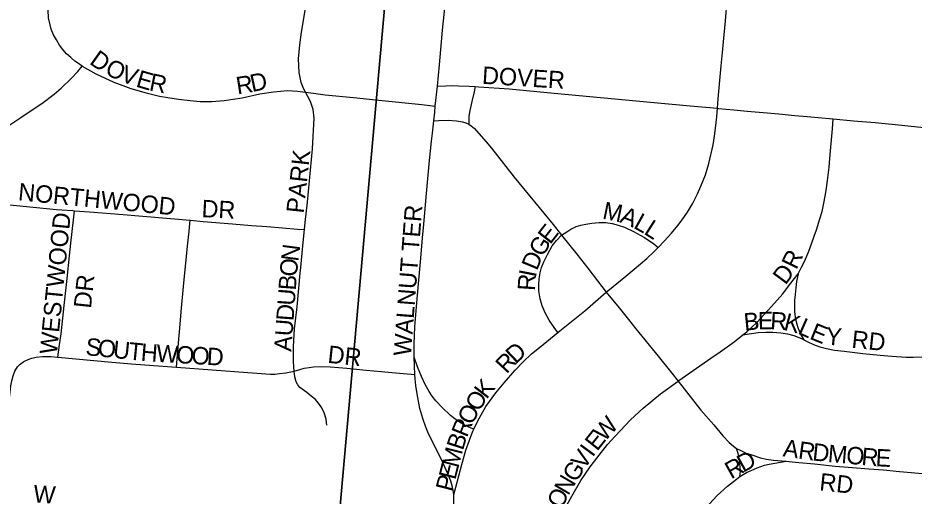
# Model space of a CAD drawing. Extents: x 1410790 to 1770854, y 566777 to 831614.
# Drawn here: x 1598681 to 1601254, y 711577 to 712950 of the extents above; entities that cross this region are included whole.
import ezdxf

# ---------------------------------------------------------------- set-up
doc = ezdxf.new("R2010")
doc.units = 0
for name, color, linetype in [('GM_X_City_Street', 7, 'Continuous'), ('GM_X_City_Street_Text', 7, 'Continuous'), ('GM_X_Section', 7, 'Continuous')]:
    doc.layers.add(name, color=color, linetype=linetype)

msp = doc.modelspace()

# ---------------------------------------------------------------- linework, layer by layer
at = {"layer": 'GM_X_City_Street'}
for points in [[(1598865.3, 712811.4), (1598854.5, 712818.6), (1598844.1, 712826), (1598832.2, 712836.3), (1598820.1, 712846.7), (1598809.7, 712858.9), (1598800.1, 712871.5), (1598790.9, 712887.2), (1598782.9, 712901.4), (1598776.4, 712917.5), (1598772.8, 712930.1), (1598768.8, 712949.7), (1598767, 712972.3), (1598767, 712997.4), (1598768.8, 713027.8), (1598772.3, 713065.1), (1598781.8, 713135.5), (1598793.9, 713218.8), (1598806.2, 713312.7), (1598811, 713349.6)], [(1599506.7, 712736.3), (1599502, 712745.5), (1599494.2, 712764.6), (1599487.7, 712793.3), (1599486.3, 712832.4), (1599489.6, 712873), (1599494.7, 712908.9), (1599499.2, 712936.5), (1599506.5, 712977.6), (1599517.3, 713026.1), (1599526.9, 713066), (1599533.4, 713090.3), (1599539.1, 713106), (1599545.4, 713118.8), (1599554.5, 713131.3)], [(1599885.1, 712754), (1599890.8, 712815.1), (1599894.9, 712859.4), (1599900.1, 712914.8), (1599904.3, 712960.1), (1599908.1, 713000.8), (1599912.1, 713043.4), (1599916.9, 713096.3)], [(1600689.3, 712690.3), (1600691.6, 712717.1), (1600695.4, 712759.4), (1600700.2, 712812.5), (1600703.9, 712850.6), (1600706.8, 712881.1), (1600712.6, 712941), (1600717.3, 713001.2), (1600718.7, 713016.4), (1600719.2, 713023)], [(1598545.1, 712428.3), (1598547.2, 712432.3), (1598553.1, 712446.6), (1598557.4, 712461), (1598559.9, 712475.1), (1598561.2, 712488.5), (1598563.6, 712510.4), (1598566.7, 712528.9), (1598570.8, 712542.6), (1598577.1, 712557.3), (1598585.1, 712571.2), (1598595.3, 712586.2), (1598605.9, 712599.9), (1598618.2, 712612.6), (1598637.2, 712629.4), (1598660.1, 712645.2), (1598689.1, 712663.7), (1598713.3, 712680.1), (1598749.6, 712704.4), (1598784.5, 712730.8), (1598805, 712748), (1598832.6, 712774.5), (1598852.7, 712796.1), (1598865.3, 712811.4)], [(1598865.3, 712811.4), (1598903.9, 712789.4), (1598956.3, 712765.6), (1599004.9, 712747.4), (1599049.2, 712734.4), (1599087.1, 712725.5), (1599111.4, 712721.2), (1599141.8, 712716.8), (1599174.8, 712712.5), (1599204.3, 712709.9), (1599237.3, 712709.9), (1599272.9, 712712.5), (1599324.1, 712720.3), (1599375.3, 712731.6), (1599414.4, 712737.7), (1599454.3, 712741.2), (1599482.9, 712739.4), (1599506.7, 712736.3)], [(1599879.1, 712696.8), (1599885.1, 712754)], [(1599885.1, 712754), (1599909, 712755.2), (1599929.6, 712755.4), (1599945.6, 712755.1), (1599976.5, 712753.6), (1599994, 712752.8)], [(1599994, 712752.8), (1599990.4, 712738), (1599983.6, 712710.2), (1599977.9, 712683.7), (1599975.7, 712667.7), (1599975.4, 712657.7), (1599975.8, 712644.8)], [(1599994, 712752.8), (1600003.6, 712752.3), (1600090.8, 712746.6), (1600220.8, 712734), (1600497.3, 712708.2), (1600611.3, 712697.7), (1600689.3, 712690.3)], [(1599503.6, 712342.1), (1599505.6, 712362.2), (1599511.6, 712420.9), (1599526.3, 712574.5), (1599531.6, 712662.3), (1599528.1, 712687.4), (1599520.3, 712709.9), (1599512.7, 712724.5), (1599506.7, 712736.3)], [(1599506.7, 712736.3), (1599528.9, 712733.4), (1599562.9, 712729.3), (1599644.6, 712721.7), (1599726.4, 712713.1), (1599840.7, 712700.9), (1599879.1, 712696.8)], [(1599874.5, 712654.7), (1599877.3, 712679.5), (1599879.1, 712696.8)], [(1600519.3, 712291), (1600537.4, 712309.9), (1600557.3, 712331.6), (1600575.5, 712354.1), (1600587.7, 712369.8), (1600603.3, 712392.3), (1600618.1, 712415.8), (1600632, 712444.4), (1600641.5, 712467), (1600654.5, 712499.1), (1600664.9, 712532.1), (1600676.8, 712585.2), (1600682.2, 712617.4), (1600687.1, 712666.2), (1600689.3, 712690.3)], [(1600689.3, 712690.3), (1600692.6, 712690), (1600736.6, 712686), (1600774.8, 712682.5), (1600820.7, 712678.3), (1600865.1, 712674.3), (1600911.9, 712670), (1600946.6, 712666.8), (1600978.9, 712663.9), (1601021.6, 712660)], [(1599818.2, 711976), (1599818.6, 712014.3), (1599820.5, 712063), (1599827, 712143.8), (1599832.8, 712207.3), (1599837.5, 712260.3), (1599842.7, 712318.5), (1599846.2, 712357.5), (1599853.2, 712435.2), (1599862.8, 712540.6), (1599868.5, 712595.6), (1599870.8, 712618.7), (1599874.5, 712654.7)], [(1599874.5, 712654.7), (1599889.1, 712655.2), (1599916, 712656.1), (1599940.3, 712654.3), (1599956.9, 712652), (1599966.8, 712648.7), (1599975.8, 712644.8)], [(1599975.8, 712644.8), (1599981.9, 712640.2), (1599991.5, 712632.3), (1600004.3, 712618.4), (1600025, 712594.1), (1600040.4, 712575.6), (1600075.1, 712531.7), (1600105.1, 712492.4), (1600217.8, 712356.7), (1600241.5, 712326)], [(1600920.9, 712215.5), (1600931.1, 712234.2), (1600939.9, 712252.5), (1600951.7, 712280.4), (1600959.4, 712301.1), (1600967.2, 712323.7), (1600973.3, 712341.1), (1600983.7, 712373.2), (1600989.8, 712394), (1600995, 712417.7), (1600998.8, 712437.7), (1601001.1, 712454.9), (1601005.5, 712482.7), (1601009.8, 712521.5), (1601012.1, 712546.2), (1601014.2, 712568.6), (1601019.2, 712631), (1601021.6, 712660)], [(1601021.6, 712660), (1601080.3, 712654.8), (1601141.7, 712649.3), (1601209.6, 712642.7), (1601291.2, 712634.6), (1601357.1, 712628), (1601395.4, 712624.2), (1601425, 712621.2), (1601461.5, 712617.6), (1601488.4, 712614.3)], [(1598545.1, 712428.3), (1598565.9, 712423.3), (1598585.7, 712420.3), (1598629.4, 712415.1), (1598666.7, 712412.2), (1598790.9, 712400.1), (1598806.4, 712398.8), (1598838.1, 712396.8), (1598842.7, 712396.4)], [(1598795.3, 711975.8), (1598800.2, 712011.2), (1598804.6, 712043.4), (1598813.3, 712124), (1598821.7, 712201.8), (1598828.7, 712266.8), (1598832.6, 712303.1), (1598839.8, 712370.1), (1598842.7, 712396.4)], [(1598842.7, 712396.4), (1598886, 712393.4), (1598982.9, 712385.6), (1599175.1, 712368.8)], [(1599136, 711947.5), (1599139.9, 711994.2), (1599142.7, 712027.7), (1599145.3, 712059.1), (1599149.2, 712105.8), (1599156.4, 712178.4), (1599162.2, 712237.3), (1599168.7, 712303.2), (1599172, 712337.3), (1599175.1, 712368.8)], [(1599175.1, 712368.8), (1599212.2, 712365.5), (1599296.3, 712358.8), (1599351, 712354.4), (1599395.2, 712350.8), (1599440.4, 712347.2), (1599483, 712343.8), (1599503.6, 712342.1)], [(1600241.5, 712326), (1600256.3, 712336.1), (1600268.6, 712343.9), (1600283.2, 712350.9), (1600297.1, 712355.2), (1600311.2, 712357.5), (1600328.3, 712360.4), (1600349.2, 712362.1), (1600368.3, 712362.1), (1600386.5, 712359.5), (1600403.7, 712355), (1600422.2, 712348.9), (1600448, 712337.1), (1600479.5, 712319.9), (1600506.3, 712301.4), (1600519.3, 712291)], [(1599474, 711935.6), (1599472.8, 711948.5), (1599471.6, 711963.4), (1599471.7, 711986.2), (1599471.7, 712007), (1599475.2, 712057.3), (1599482.3, 712120.2), (1599491.2, 712217), (1599492.5, 712233.1), (1599498.8, 712295.2), (1599503.6, 712342.1)], [(1600231.1, 712046.4), (1600220.6, 712060.9), (1600206.4, 712081.9), (1600194.7, 712102.9), (1600186, 712123.2), (1600180.5, 712143.6), (1600176.6, 712166.7), (1600176.2, 712183.6), (1600177.5, 712200.7), (1600180.5, 712218.2), (1600184.2, 712233.6), (1600191, 712249.6), (1600200.8, 712270.6), (1600214.7, 712295.4), (1600226.7, 712311.2), (1600241.5, 712326)], [(1600241.5, 712326), (1600285.2, 712271.9), (1600316.9, 712231), (1600344.7, 712195.1), (1600369.9, 712162.6)], [(1600369.9, 712162.6), (1600389.7, 712178.9), (1600425.9, 712208.7), (1600450.5, 712228.3), (1600486.1, 712259.5), (1600507, 712278.6), (1600519.3, 712291)], [(1600761.7, 712039.8), (1600773.6, 712049.1), (1600802.3, 712075.5), (1600844.1, 712121.1), (1600876.6, 712157.8), (1600896.4, 712183.7), (1600920.9, 712215.5)], [(1600920.9, 712215.5), (1600916.6, 712193.3), (1600914.2, 712175.5), (1600912.4, 712156), (1600910.7, 712139), (1600910.7, 712122.8), (1600910.7, 712106.7), (1600912.4, 712090.5), (1600915.9, 712073.5), (1600920.9, 712058.2), (1600928.6, 712040.3), (1600937, 712026.2)], [(1600231.1, 712046.4), (1600236.9, 712051.2), (1600308.5, 712109.2), (1600369.9, 712162.6)], [(1600369.9, 712162.6), (1600406.8, 712117.2), (1600433.5, 712084.5), (1600455.3, 712057.7), (1600518.7, 711979.1), (1600558.4, 711929.8), (1600576.5, 711907.4)], [(1599989.5, 711769), (1600001.8, 711795.1), (1600010.4, 711810.7), (1600024.3, 711834.2), (1600053, 711873.2), (1600076.6, 711902), (1600108.7, 711939.1), (1600131.6, 711962.6), (1600155.3, 711985.2), (1600178.4, 712003.8), (1600231.1, 712046.4)], [(1600576.5, 711907.4), (1600578.2, 711908.7), (1600670.7, 711973.1), (1600697.5, 711991.4), (1600737, 712020.2), (1600761.7, 712039.8)], [(1600761.7, 712039.8), (1600780.8, 712042.8), (1600806.3, 712046.7), (1600827.8, 712047.6), (1600848.6, 712047.6), (1600871.7, 712046), (1600890.9, 712042.8), (1600908.4, 712038), (1600930.8, 712029.2), (1600937, 712026.2)], [(1600937, 712026.2), (1600949.2, 712020.4), (1600965.1, 712012.4), (1600983.5, 712005.2), (1601002.6, 712000.4), (1601025.8, 711996.4), (1601052.9, 711993.3), (1601107.2, 711986.9), (1601156.7, 711982.1), (1601190.2, 711978.9), (1601230.9, 711975.7), (1601251.7, 711975.7), (1601285.2, 711976.5), (1601314.3, 711977.2)], [(1598652.3, 711823.5), (1598658.1, 711876.3), (1598660.2, 711893.4), (1598662.6, 711908.1), (1598666.5, 711922.8), (1598671.6, 711935.4), (1598679.4, 711948.2), (1598686.9, 711956.3), (1598697.7, 711963.8), (1598709.7, 711969.2), (1598720.8, 711973.4), (1598732.5, 711976.1), (1598750.8, 711978.1), (1598775.4, 711977.5), (1598795.3, 711975.8)], [(1598795.3, 711975.8), (1598950.6, 711961.6), (1599006.6, 711957.1), (1599045.3, 711954.1), (1599136, 711947.5)], [(1599820.4, 711926.2), (1599818.2, 711976)], [(1599989.5, 711769), (1599982, 711772.4), (1599964.6, 711780.2), (1599948.1, 711789.8), (1599934.9, 711798.9), (1599922.4, 711808.9), (1599899.1, 711831.2), (1599880.7, 711850.2), (1599870, 711864.1), (1599861.4, 711877.1), (1599850.2, 711897.3), (1599839.6, 711920.8), (1599828.4, 711948.6), (1599818.2, 711976)], [(1599474, 711935.6), (1599490.3, 711940.5), (1599502.9, 711944), (1599516.5, 711946.8), (1599528.9, 711948.6), (1599552.3, 711949.3), (1599577.6, 711948.4), (1599625.3, 711944), (1599680.7, 711939), (1599724.1, 711935), (1599754.6, 711932.2), (1599788.2, 711929.1), (1599820.4, 711926.2)], [(1599136, 711947.5), (1599340.8, 711931.8), (1599405.6, 711927.5), (1599418.6, 711927.6), (1599431.7, 711928.7), (1599450, 711930.7), (1599474, 711935.6)], [(1599567.6, 711780.7), (1599565.4, 711797.8), (1599560.1, 711816.2), (1599553.1, 711831), (1599543.3, 711844.1), (1599534.7, 711854), (1599522.9, 711864), (1599509.9, 711874.5), (1599496.4, 711884), (1599490.5, 711889), (1599484.3, 711896.2), (1599479.4, 711905.2), (1599476.1, 711919.5), (1599474, 711935.6)], [(1599932.6, 711581.4), (1599930.6, 711593.1), (1599927.2, 711606.4), (1599923.3, 711619.7), (1599917.7, 711634.3), (1599911, 711650), (1599896.7, 711682.4), (1599872.4, 711731), (1599858, 711760.3), (1599851.9, 711775.2), (1599843.1, 711800.2), (1599834.4, 711828.8), (1599826.6, 711870.5), (1599822.9, 711895), (1599821.1, 711913.4), (1599820.4, 711926.2)], [(1600202.5, 711408.4), (1600207.3, 711430.4), (1600216.3, 711457.3), (1600230.1, 711492.5), (1600239.1, 711514.5), (1600252.2, 711542.3), (1600271, 711577.4), (1600297.1, 711622.4), (1600324.1, 711661.6), (1600342.7, 711686.5), (1600373.1, 711725), (1600395.1, 711749.2), (1600439.8, 711796.2), (1600475.5, 711829.4), (1600526.1, 711870.7), (1600576.5, 711907.4)], [(1600576.5, 711907.4), (1600641.8, 711824.1), (1600678.6, 711781.6), (1600704.4, 711750.3), (1600722.8, 711731), (1600735.1, 711720.4), (1600744.4, 711714.2)], [(1599932.6, 711581.4), (1599937.7, 711603.1), (1599955.1, 711668.2), (1599967.2, 711709), (1599977.7, 711737.7), (1599987.2, 711763.7), (1599989.5, 711769)], [(1600744.4, 711714.2), (1600758.1, 711707), (1600771.8, 711700.8), (1600787.6, 711695.3), (1600813, 711687.4), (1600829.4, 711683.6), (1600850.7, 711680.6), (1600886.5, 711677.2)], [(1600754, 711633.2), (1600755, 711648.3), (1600754.4, 711661.5), (1600751.7, 711683.8), (1600748.8, 711699.4), (1600744.4, 711714.2)], [(1600754, 711633.2), (1600773, 711644.6), (1600786.1, 711650.5), (1600803, 711657.9), (1600824, 711665.5), (1600837.7, 711668.9), (1600853.8, 711671.6), (1600886.5, 711677.2)], [(1600886.5, 711677.2), (1600904.3, 711675.5), (1600923.1, 711674), (1600967.5, 711669.5), (1601027.4, 711663.5), (1601076.8, 711659.5), (1601123.7, 711655.7), (1601166.2, 711652.5), (1601212.3, 711647.9), (1601246, 711644.7), (1601277.4, 711641.8), (1601317.3, 711638.3), (1601373.7, 711633.9), (1601377.6, 711633.6)], [(1600541.3, 711374.7), (1600544.7, 711385.9), (1600551.7, 711404.2), (1600558.6, 711418.1), (1600569, 711438.9), (1600582.1, 711458.8), (1600595.9, 711477.9), (1600609.8, 711494.4), (1600655.9, 711543.9), (1600688.8, 711578.6), (1600718.5, 711605.3), (1600743.7, 711625.9), (1600754, 711633.2)], [(1599918, 711434.8), (1599919.7, 711440.9), (1599923.8, 711457.5), (1599927.1, 711480.9), (1599929.1, 711508.5), (1599931.7, 711548.4), (1599932.5, 711560.6), (1599932.6, 711581.4)]]:
    msp.add_lwpolyline(points, dxfattribs=at)
at = {"layer": 'GM_X_Section'}
for points in [[(1599854.3, 714342.5), (1599376.7, 708982.6), (1594039.9, 709527.8), (1594520.4, 714823.7)], [(1599854.3, 714342.5), (1605148.2, 713864), (1604648.8, 708516.3), (1599376.7, 708982.6)]]:
    msp.add_lwpolyline(points, close=True, dxfattribs=at)

# ---------------------------------------------------------------- texts
at = {"layer": 'GM_X_City_Street_Text'}
for s, rotation, p in [('D', 324.7698, (1598883.4, 712819.7)), ('O', 334.9662, (1598927.7, 712789.5)), ('V', 340.5531, (1598972.5, 712768.8)), ('E', 343.7612, (1599016.9, 712753.2)), ('DOVER', 356.4257, (1600012.3, 712760.9)), ('R', 348.688, (1599055.3, 712742.2)), ('R', 8.8274, (1599311, 712730)), ('D', 12.0767, (1599353.1, 712736.7)), ('PARK', 83.8278, (1599500.8, 712387.3)), ('NORTHWOOD', 354.4742, (1598679.7, 712426.5)), ('DR', 356.989, (1599207, 712378.1)), ('M', 348.39, (1600356.7, 712374)), ('WESTWOOD', 84.3606, (1598792.4, 711982.3)), ('WALNUT TER', 85.6013, (1599808.7, 711977.8)), ('A', 337.8089, (1600406, 712364.1)), ('L', 330.9905, (1600445.4, 712348.2)), ('E', 52.0483, (1600208.8, 712297.6)), ('L', 327.4618, (1600475.4, 712331.5)), ('G', 58.845, (1600186.9, 712261.2)), ('N', 82.5469, (1599485.4, 712249)), ('R', 64.165, (1600916, 712225)), ('O', 84.5047, (1599481.2, 712205.7)), ('D', 67.5735, (1600171, 712222.4)), ('D', 53.3443, (1600884.5, 712181.1)), ('DR', 83.9934, (1598890.2, 712114.4)), ('B', 85.8192, (1599478.3, 712166.5)), ('R', 86.2328, (1600165.1, 712165.5)), ('I', 78.7329, (1600167.5, 712203.2)), ('U', 85.8209, (1599475.1, 712122.6)), ('D', 85.8209, (1599471.9, 712078.7)), ('B', 5.4714, (1600767.3, 712051.8)), ('E', 1.202, (1600805.8, 712055.6)), ('R', 357.1813, (1600840.1, 712056.3)), ('U', 85.8209, (1599468.7, 712034.9)), ('K', 345.6191, (1600877, 712054.8)), ('L', 336.0264, (1600917.5, 712044.6)), ('E', 337.7085, (1600951.1, 712029.6)), ('Y', 354.6655, (1600999, 712012.5)), ('RD', 353.9832, (1601073, 712003.5)), ('S', 354.1698, (1598873.1, 711982.1)), ('O', 354.1684, (1598908.1, 711978.5)), ('A', 85.8209, (1599465.5, 711991)), ('U', 354.1546, (1598951.9, 711974.1)), ('T', 354.276, (1598995.8, 711969.6)), ('H', 355.7815, (1599032.2, 711965.9)), ('W', 356.6091, (1599076.9, 711962.7)), ('O', 356.649, (1599134, 711959.2)), ('O', 356.6323, (1599177.9, 711956.7)), ('D', 356.6323, (1599221.9, 711954.1)), ('DR', 353.9946, (1599568.3, 711960.1)), ('D', 43.547, (1600110.1, 711954.5)), ('R', 47.233, (1600083.8, 711926.1)), ('K', 52.0502, (1600026.2, 711853.2)), ('O', 58.5901, (1600004.1, 711816.9)), ('O', 62.6334, (1599984.3, 711778.7)), ('R', 68.0002, (1599970, 711743.1)), ('W', 47.6403, (1600364.9, 711731)), ('B', 71.7724, (1599957.9, 711706.3)), ('E', 51.4682, (1600343.6, 711704.1)), ('M', 75.6987, (1599945.2, 711656)), ('I', 53.5934, (1600330.8, 711686.8)), ('A', 351.9286, (1600875.5, 711691.6)), ('R', 352.1437, (1600919.2, 711685.4)), ('D', 354.0682, (1600960.3, 711679.8)), ('M', 355.0076, (1601004.9, 711675.2)), ('O', 355.049, (1601057.6, 711670.6)), ('V', 55.9947, (1600306.5, 711650.8)), ('D', 29.0291, (1600763.2, 711643.9)), ('R', 355.0387, (1601101.4, 711666.8)), ('E', 356.634, (1601142.4, 711663.2)), ('E', 75.7406, (1599936.5, 711621.9)), ('G', 57.2556, (1600282.9, 711614)), ('R', 29.3022, (1600728.7, 711624.5)), ('RD', 353.9934, (1600980.6, 711593.9)), ('P', 75.6987, (1599927.8, 711587.7)), ('N', 59.7373, (1600261, 711576.5)), ('W', 355.6026, (1598723.3, 711559.7)), ('O', 63.347, (1600241.7, 711537.9))]:
    msp.add_text(s, height=50, rotation=rotation, dxfattribs=at).set_placement(p)

doc.saveas('drawing.dxf')
